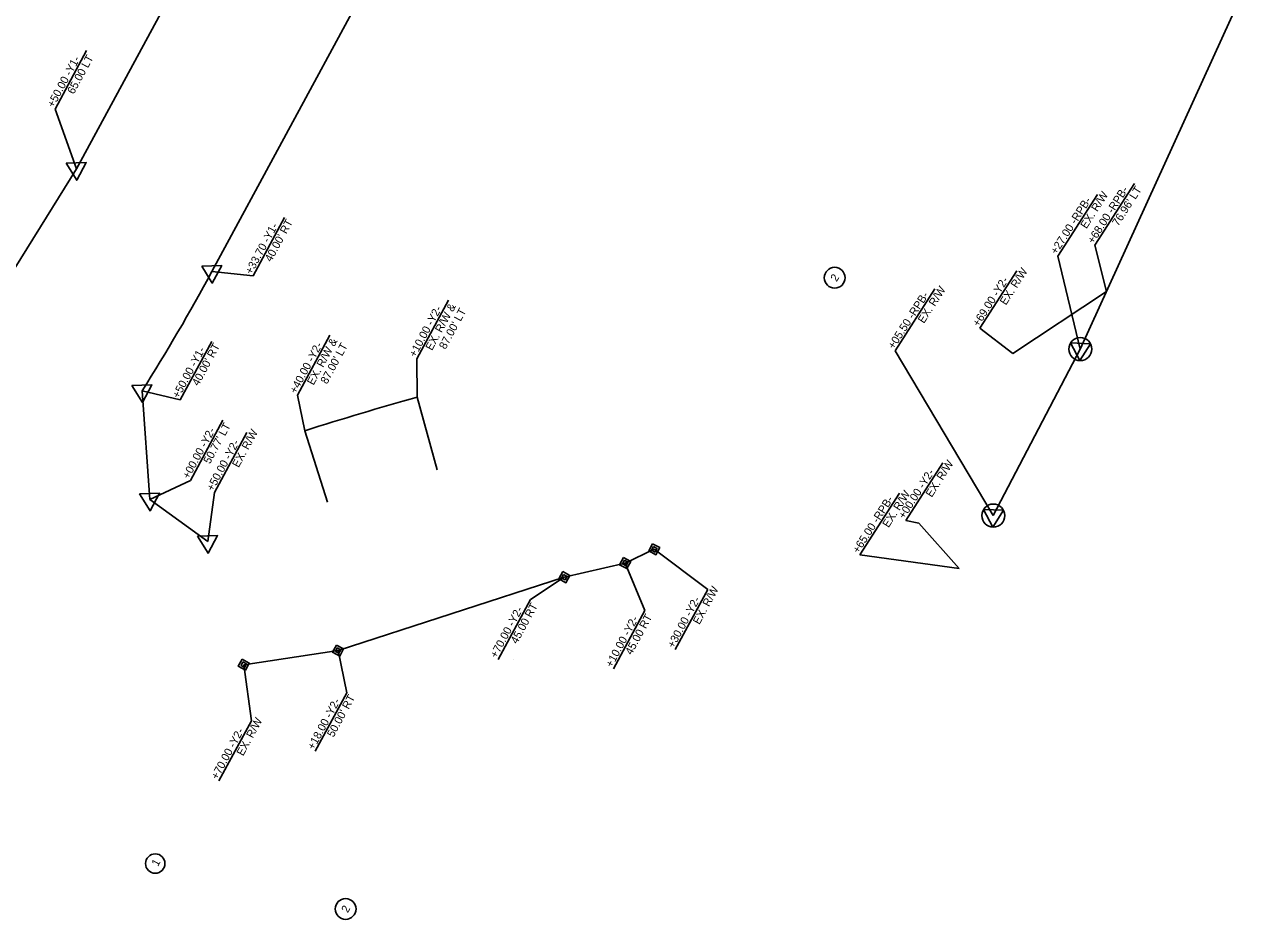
# Model space of a CAD drawing. Extents: x 2345854 to 2349056, y 842589 to 845145.
# Drawn here: x 2346609 to 2347378, y 842937 to 843495 of the extents above; entities that cross this region are included whole.
import ezdxf

# ---------------------------------------------------------------- set-up
doc = ezdxf.new("R2010")
doc.units = 0
for name, color, linetype in [('Prop Easement Construction', 7, 'Continuous'), ('Prop Easement Construction Station Offsets', 7, 'Continuous'), ('Prop Easement Permanent Drainage', 7, 'Continuous'), ('Prop Easement Permanent Drainage Station Offsets', 7, 'Continuous'), ('Prop Parcel Number Text', 7, 'Continuous'), ('Prop ROW Marker CELL', 7, 'Continuous'), ('Prop ROW RW CA Lines', 7, 'Continuous'), ('Prop ROW RW Lines', 7, 'Continuous'), ('Prop ROW Station Offsets', 7, 'Continuous')]:
    doc.layers.add(name, color=color, linetype=linetype)

msp = doc.modelspace()

# ---------------------------------------------------------------- linework, layer by layer
at = {"layer": 'Prop Easement Construction'}
for p, q in [((2347226.43, 843290.13), (2347284.91, 843328.84)), ((2346866.64, 843217.39), (2346854.03, 843262.73)), ((2346798.07, 843197.15), (2346783.84, 843241.79)), ((2347192.82, 843155.8), (2347167.52, 843184.17)), ((2346914.44, 843098.87), (2346914.44, 843098.87))]:
    msp.add_line(p, q, dxfattribs=at)
msp.add_arc((2347378.3, 841377.27), 1957, 105.53909, 107.68385, dxfattribs=at)
at = {"layer": 'Prop Easement Construction Station Offsets'}
for p, q in [((2347302.3, 843396.12), (2347277.6, 843357.6)), ((2347228.82, 843341.71), (2347205.78, 843305.79)), ((2346873.62, 843323.25), (2346853.9, 843286.76)), ((2346799.58, 843301.59), (2346779.29, 843264.04)), ((2347182.48, 843221.69), (2347159.44, 843185.77)), ((2347155.47, 843202.74), (2347130.76, 843164.21))]:
    msp.add_line(p, q, dxfattribs=at)
for points in [[(2347277.6, 843357.6), (2347284.91, 843328.84)], [(2347205.78, 843305.79), (2347226.43, 843290.13)], [(2346853.9, 843286.76), (2346854.03, 843262.73)], [(2346779.29, 843264.04), (2346783.84, 843241.79)], [(2347159.44, 843185.77), (2347167.52, 843184.17)], [(2347130.76, 843164.21), (2347192.82, 843155.8)]]:
    msp.add_lwpolyline(points, dxfattribs=at)
at = {"layer": 'Prop Easement Permanent Drainage'}
for p, q in [((2346984.08, 843159.18), (2347002.21, 843167.79)), ((2346946.05, 843150.34), (2346984.08, 843159.18)), ((2346804.69, 843104.52), (2346946.05, 843150.34)), ((2346745.75, 843095.7), (2346804.69, 843104.52))]:
    msp.add_line(p, q, dxfattribs=at)
at = {"layer": 'Prop Easement Permanent Drainage Station Offsets'}
for p, q in [((2347035.65, 843142.68), (2347015.36, 843105.13)), ((2346924.89, 843136.45), (2346904.6, 843098.91)), ((2346996.45, 843129.53), (2346976.73, 843093.04)), ((2346810.15, 843078.13), (2346790.43, 843041.64)), ((2346750.5, 843060.6), (2346730.21, 843023.05))]:
    msp.add_line(p, q, dxfattribs=at)
for points in [[(2347001.18, 843171.24), (2347005.66, 843168.81), (2347003.24, 843164.34), (2346998.76, 843166.76)], [(2347001.7, 843169.51), (2347003.94, 843168.3), (2347002.73, 843166.06), (2347000.49, 843167.27)], [(2346983.05, 843162.63), (2346987.53, 843160.21), (2346985.1, 843155.73), (2346980.63, 843158.15)], [(2346983.56, 843160.9), (2346985.8, 843159.69), (2346984.59, 843157.45), (2346982.35, 843158.66)], [(2346945.02, 843153.79), (2346949.5, 843151.37), (2346947.08, 843146.89), (2346942.6, 843149.31)], [(2346945.54, 843152.06), (2346947.78, 843150.85), (2346946.57, 843148.61), (2346944.33, 843149.82)], [(2346803.66, 843107.97), (2346808.14, 843105.55), (2346805.72, 843101.07), (2346801.24, 843103.49)], [(2346804.18, 843106.24), (2346806.42, 843105.03), (2346805.21, 843102.79), (2346802.97, 843104)], [(2346744.72, 843099.15), (2346749.2, 843096.72), (2346746.78, 843092.25), (2346742.3, 843094.67)], [(2346745.23, 843097.42), (2346747.47, 843096.21), (2346746.26, 843093.97), (2346744.02, 843095.18)]]:
    msp.add_lwpolyline(points, close=True, dxfattribs=at)
for points in [[(2347035.65, 843142.68), (2347002.21, 843167.79)], [(2346996.45, 843129.53), (2346984.08, 843159.18)], [(2346924.89, 843136.45), (2346946.05, 843150.34)], [(2346810.15, 843078.13), (2346804.69, 843104.52)], [(2346750.5, 843060.6), (2346745.75, 843095.7)]]:
    msp.add_lwpolyline(points, dxfattribs=at)
at = {"layer": 'Prop Parcel Number Text'}
for centre, radius in [((2347115.01, 843337.37), 6.49), ((2346690.4, 842971.47), 6.05), ((2346809.37, 842943.11), 6.49)]:
    msp.add_circle(centre, radius, dxfattribs=at)
at = {"layer": 'Prop ROW Marker CELL'}
for p, q in [((2346641.17, 843405.47), (2346641.17, 843405.47)), ((2346725.79, 843341.21), (2346725.79, 843341.21)), ((2347268.49, 843292.81), (2347268.49, 843292.81)), ((2346682.21, 843266.65), (2346682.21, 843266.65)), ((2346687, 843198.95), (2346687, 843198.95)), ((2347214.12, 843188.81), (2347214.12, 843188.81)), ((2346723.19, 843172.53), (2346723.19, 843172.53)), ((2347002.21, 843167.79), (2347002.21, 843167.79)), ((2346984.08, 843159.18), (2346984.08, 843159.18)), ((2346946.05, 843150.34), (2346946.05, 843150.34)), ((2346804.69, 843104.52), (2346804.69, 843104.52)), ((2346745.75, 843095.7), (2346745.75, 843095.7))]:
    msp.add_line(p, q, dxfattribs=at)
for points in [[(2346634.83, 843408.92), (2346647.3, 843409.24), (2346641.37, 843398.26)], [(2346719.45, 843344.65), (2346731.92, 843344.98), (2346725.99, 843334)], [(2347268.14, 843285.6), (2347262.43, 843296.7), (2347274.89, 843296.13)], [(2346675.87, 843270.09), (2346688.35, 843270.42), (2346682.41, 843259.44)], [(2346680.66, 843202.39), (2346693.13, 843202.71), (2346687.2, 843191.74)], [(2347213.77, 843181.6), (2347208.05, 843192.7), (2347220.52, 843192.13)], [(2346716.85, 843175.97), (2346729.33, 843176.3), (2346723.39, 843165.32)]]:
    msp.add_lwpolyline(points, close=True, dxfattribs=at)
for centre in [(2347268.49, 843292.81), (2347214.12, 843188.81)]:
    msp.add_circle(centre, 7.2, dxfattribs=at)
at = {"layer": 'Prop ROW RW CA Lines'}
for p, q in [((2347268.49, 843292.81), (2347377.9, 843532.91)), ((2347214.12, 843188.81), (2347268.49, 843292.81))]:
    msp.add_line(p, q, dxfattribs=at)
at = {"layer": 'Prop ROW RW Lines'}
for p, q in [((2346725.79, 843341.21), (2347066.34, 843971.38)), ((2346641.17, 843405.47), (2346867, 843823.36)), ((2346484.79, 843153.91), (2346641.17, 843405.47)), ((2346687, 843198.95), (2346682.21, 843266.65)), ((2346723.19, 843172.53), (2346687, 843198.95))]:
    msp.add_line(p, q, dxfattribs=at)
msp.add_arc((2345590.91, 843954.52), 1290, 327.77594, 331.61241, dxfattribs=at)
at = {"layer": 'Prop ROW Station Offsets'}
for p, q in [((2346647.53, 843479.22), (2346627.81, 843442.73)), ((2347279.16, 843389.44), (2347254.45, 843350.91)), ((2346771.26, 843375.01), (2346751.54, 843338.52)), ((2347177.67, 843330.41), (2347152.81, 843291.64)), ((2346725.73, 843297.56), (2346706.01, 843261.07)), ((2346732.64, 843248.3), (2346712.35, 843210.75)), ((2346747.71, 843240.7), (2346727.42, 843203.15))]:
    msp.add_line(p, q, dxfattribs=at)
for points in [[(2346627.81, 843442.73), (2346641.17, 843405.47)], [(2347254.45, 843350.91), (2347268.49, 843292.81)], [(2346751.54, 843338.52), (2346725.79, 843341.21)], [(2347152.81, 843291.64), (2347214.12, 843188.81)], [(2346706.01, 843261.07), (2346682.21, 843266.65)], [(2346712.35, 843210.75), (2346687, 843198.95)], [(2346727.42, 843203.15), (2346723.19, 843172.53)]]:
    msp.add_lwpolyline(points, dxfattribs=at)

# ---------------------------------------------------------------- texts
at = {"layer": 'Prop Easement Construction Station Offsets'}
for s, rotation, p in [('+68.00 -RPB-', 57.32812, (2347276.72, 843358.16)), ("76.96' LT", 57.32812, (2347292.19, 843369.16)), ('+69.00 -Y2-', 57.32812, (2347204.91, 843306.35)), ('EX. R/W', 57.32812, (2347221.99, 843319.86)), ('+10.00 -Y2-', 61.61241, (2346852.98, 843287.26)), ('EX. R/W &', 61.61241, (2346863.34, 843291.52)), ("87.00' LT", 61.61241, (2346871.78, 843292.24)), ('EX. R/W &', 61.61241, (2346789.3, 843269.86)), ('+40.00 -Y2-', 61.61241, (2346778.37, 843264.54)), ("87.00' LT", 61.61241, (2346797.74, 843270.57)), ('EX. R/W', 57.32812, (2347175.64, 843199.84)), ('+00.00 -Y2-', 57.32812, (2347158.57, 843186.33)), ('+65.00 -RPB-', 57.32812, (2347129.89, 843164.78)), ('EX. R/W', 57.32812, (2347148.64, 843180.89))]:
    msp.add_text(s, height=5, rotation=rotation, dxfattribs=at).set_placement(p)
at = {"layer": 'Prop Easement Permanent Drainage Station Offsets'}
for s, p in [('EX. R/W', (2347030.47, 843120.38)), ('+30.00 -Y2-', (2347014.44, 843105.63)), ('+70.00 -Y2-', (2346903.68, 843099.4)), ('45.00 RT', (2346916.53, 843108.28)), ('+10.00 -Y2-', (2346975.81, 843093.54)), ('45.00 RT', (2346988.1, 843101.37)), ("50.00' RT", (2346801.8, 843049.96)), ('+18.00 -Y2-', (2346789.51, 843042.13)), ('EX. R/W', (2346745.32, 843038.3)), ('+70.00 -Y2-', (2346729.3, 843023.55))]:
    msp.add_text(s, height=5, rotation=61.61241, dxfattribs=at).set_placement(p)
at = {"layer": 'Prop Parcel Number Text'}
for s, rotation, p in [('2', 57.32812, (2347116.15, 843334.53)), ('1', 61.61241, (2346692.09, 842969.34)), ('2', 61.61241, (2346810.73, 842940.36))]:
    msp.add_text(s, height=5, rotation=rotation, dxfattribs=at).set_placement(p)
at = {"layer": 'Prop ROW Station Offsets'}
for s, rotation, p in [('65.00 LT', 61.61241, (2346639.46, 843451.58)), ('+50.00 -Y1-', 61.61241, (2346626.89, 843443.23)), ('EX. R/W', 57.32812, (2347272.32, 843367.59)), ('+27.00 -RPB-', 57.32812, (2347253.58, 843351.48)), ('+33.70 -Y1-', 61.61241, (2346750.62, 843339.02)), ("40.00' RT", 61.61241, (2346762.9, 843346.85)), ('EX. R/W', 57.32812, (2347170.76, 843308.44)), ('+05.50 -RPB-', 57.32812, (2347152.01, 843292.32)), ('+50.00 -Y1-', 61.61241, (2346705.09, 843261.57)), ("40.00' RT", 61.61241, (2346717.38, 843269.4)), ("50.77' LT", 61.61241, (2346724.56, 843220.65)), ('+00.00 -Y2-', 61.61241, (2346711.43, 843211.25)), ('EX. R/W', 61.61241, (2346742.52, 843218.4)), ('+50.00 -Y2-', 61.61241, (2346726.5, 843203.65))]:
    msp.add_text(s, height=5, rotation=rotation, dxfattribs=at).set_placement(p)

doc.saveas('drawing.dxf')
